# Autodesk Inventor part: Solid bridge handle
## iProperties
Shininess: 64.0
Length Units: 11269
Angle Units: 11279
Time Units: 11290
Mass Units: 11283
Length Display Precision: 3
Angle Display Precision: 2
Compacted: True
Part Number: Solid bridge handle
Document SubType Name: Modeling
Created: 2004-02
Material: ABS Plastic
Designer: Erik Kerkhoven
Manufacturer: Standard
Standards Organization: Custom
Density: 0.0
Volumn: 0.0
Area: 0.0
PropertySet Name: Model Information
Control State: 0
Master: False
Checked Out: False
Author: Erik Kerkhoven
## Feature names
1. Sweep1
2. Hole1
